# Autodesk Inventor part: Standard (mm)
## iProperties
Part Number: Standard (mm)
Document SubType Name: Modeling
Created: 2002-07
Density: 1 g/cm^3
Control State: 0
Master: False
Checked Out: False
Shininess: 64.0
Length Units: 11269
Angle Units: 11279
Time Units: 11290
Mass Units: 11283
Length Display Precision: 3
Angle Display Precision: 2
Compacted: True
Density: 0.0
Volumn: 0.0
Area: 0.0
PropertySet Name: Model Information
